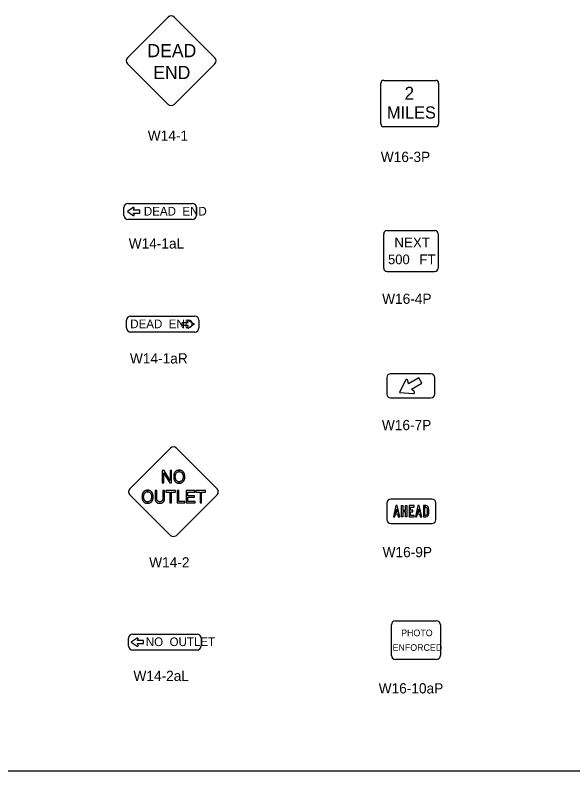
# Model space of a CAD drawing. Extents: x 42133 to 45533, y 41351 to 47951.
# Drawn here: x 44235 to 44644, y 45801 to 46356 of the extents above; entities that cross this region are included whole.
import ezdxf

# ---------------------------------------------------------------- set-up
doc = ezdxf.new("R2010")
doc.units = 0
doc.layers.add('P_ODOT_PLAN_Border', color=7, linetype='Continuous')
doc.layers.add('P_TRAF_SIGN_SignDetails', color=7, linetype='Continuous')

msp = doc.modelspace()

# ---------------------------------------------------------------- linework, layer by layer
at = {"layer": 'P_ODOT_PLAN_Border'}
msp.add_lwpolyline([(43908.34, 45801.35), (45508.34, 45801.35), (45508.34, 46801.35), (43908.34, 46801.35)], close=True, dxfattribs=at)
at = {"layer": 'P_TRAF_SIGN_SignDetails'}
for p, q in [((44347.15, 46354.48), (44317.28, 46324.61)), ((44381.29, 46324.61), (44351.41, 46354.48)), ((44317.28, 46320.35), (44347.15, 46290.47)), ((44351.41, 46290.47), (44381.29, 46320.35)), ((44505.11, 46308.09), (44543.26, 46308.09)), ((44502.98, 46276.17), (44502.98, 46305.97)), ((44545.38, 46305.97), (44545.38, 46276.17)), ((44543.26, 46274.04), (44505.11, 46274.04)), ((44317.61, 46217.76), (44364.73, 46217.76)), ((44314.61, 46209.04), (44314.61, 46214.77)), ((44367.71, 46214.77), (44367.71, 46209.04)), ((44364.73, 46206.04), (44317.61, 46206.04)), ((44505.12, 46170.38), (44505.12, 46195.37)), ((44507.62, 46197.86), (44542.6, 46197.86)), ((44545.1, 46195.37), (44545.1, 46170.38)), ((44507.62, 46167.88), (44542.6, 46167.88)), ((44319.52, 46135.13), (44366.65, 46135.13)), ((44316.53, 46126.41), (44316.53, 46132.13)), ((44369.63, 46132.13), (44369.63, 46126.41)), ((44366.65, 46123.41), (44319.52, 46123.41)), ((44507.31, 46090.01), (44507.31, 46077.92)), ((44539.76, 46092.76), (44510.06, 46092.76)), ((44542.51, 46077.92), (44542.51, 46090.01)), ((44510.06, 46075.17), (44539.76, 46075.17)), ((44348.81, 46038.16), (44318.94, 46008.29)), ((44382.95, 46008.29), (44353.07, 46038.16)), ((44318.94, 46004.03), (44348.81, 45974.15)), ((44353.07, 45974.15), (44382.95, 46004.03)), ((44507.5, 45997.93), (44507.5, 45985.61)), ((44540.57, 46000.74), (44510.3, 46000.74)), ((44543.37, 45985.61), (44543.37, 45997.93)), ((44510.3, 45982.8), (44540.57, 45982.8)), ((44510.74, 45886.07), (44510.74, 45908.5)), ((44513.73, 45911.5), (44543.67, 45911.5)), ((44546.66, 45908.5), (44546.66, 45886.07)), ((44321.09, 45901.78), (44368.21, 45901.78)), ((44318.09, 45893.05), (44318.09, 45898.78)), ((44371.19, 45898.78), (44371.19, 45893.05)), ((44368.21, 45890.06), (44321.09, 45890.06)), ((44543.67, 45883.08), (44513.73, 45883.08))]:
    msp.add_line(p, q, dxfattribs=at)
for points in [[(44321.5, 46214.77), (44317.23, 46211.84), (44321.5, 46208.92)], [(44321.5, 46214.77), (44317.23, 46211.84), (44321.5, 46208.92)], [(44321.5, 46214.77), (44317.23, 46211.84), (44321.5, 46208.92)], [(44326.23, 46210.73), (44326.23, 46212.96), (44321.76, 46212.96), (44322.16, 46214.28)], [(44326.23, 46210.73), (44326.23, 46212.96), (44321.76, 46212.96), (44322.16, 46214.28)], [(44326.23, 46210.73), (44326.23, 46212.96), (44321.76, 46212.96), (44322.16, 46214.28)], [(44322.16, 46209.4), (44321.76, 46210.73), (44326.23, 46210.73)], [(44322.16, 46209.4), (44321.76, 46210.73), (44326.23, 46210.73)], [(44322.16, 46209.4), (44321.76, 46210.73), (44326.23, 46210.73)], [(44357.3, 46128.1), (44357.3, 46130.32), (44361.78, 46130.32), (44361.37, 46131.65)], [(44357.3, 46128.1), (44357.3, 46130.32), (44361.78, 46130.32), (44361.37, 46131.65)], [(44357.3, 46128.1), (44357.3, 46130.32), (44361.78, 46130.32), (44361.37, 46131.65)], [(44362.03, 46132.14), (44366.3, 46129.21), (44362.03, 46126.29)], [(44362.03, 46132.14), (44366.3, 46129.21), (44362.03, 46126.29)], [(44362.03, 46132.14), (44366.3, 46129.21), (44362.03, 46126.29)], [(44361.37, 46126.77), (44361.78, 46128.1), (44357.3, 46128.1)], [(44361.37, 46126.77), (44361.78, 46128.1), (44357.3, 46128.1)], [(44361.37, 46126.77), (44361.78, 46128.1), (44357.3, 46128.1)], [(44521.12, 46088.14), (44516.75, 46079.01), (44526.84, 46078.24)], [(44533.07, 46085.92), (44530.9, 46089.69), (44523.32, 46085.32), (44522.71, 46087.96)], [(44527.48, 46079.7), (44525.49, 46081.55), (44533.07, 46085.92)], [(44536.11, 45988.89), (44535.23, 45988.89), (44535.23, 45995.99), (44534.2, 45995.99), (44534.2, 45987.74), (44535.23, 45987.74), (44536.11, 45987.74)], [(44536.11, 45995.99), (44535.23, 45995.99), (44535.23, 45994.84), (44536.11, 45994.84)], [(44324.3, 45898.78), (44320.03, 45895.86), (44324.3, 45892.93)], [(44324.3, 45898.78), (44320.03, 45895.86), (44324.3, 45892.93)], [(44324.3, 45898.78), (44320.03, 45895.86), (44324.3, 45892.93)], [(44329.03, 45894.74), (44329.03, 45896.97), (44324.55, 45896.97), (44324.96, 45898.3)], [(44329.03, 45894.74), (44329.03, 45896.97), (44324.55, 45896.97), (44324.96, 45898.3)], [(44329.03, 45894.74), (44329.03, 45896.97), (44324.55, 45896.97), (44324.96, 45898.3)], [(44324.96, 45893.42), (44324.55, 45894.74), (44329.03, 45894.74)], [(44324.96, 45893.42), (44324.55, 45894.74), (44329.03, 45894.74)], [(44324.96, 45893.42), (44324.55, 45894.74), (44329.03, 45894.74)]]:
    msp.add_lwpolyline(points, dxfattribs=at)
for points in [[(44342.76, 46021.78), (44342.76, 46012.69), (44343.88, 46012.69), (44343.88, 46020.06), (44343.94, 46019.89), (44344.02, 46019.71), (44344.11, 46019.54), (44344.2, 46019.38), (44348.32, 46012.69), (44349.6, 46012.69), (44349.6, 46021.78), (44348.48, 46021.78), (44348.48, 46014.41), (44348.39, 46014.61), (44348.3, 46014.81), (44348.2, 46015), (44348.08, 46015.18), (44344.05, 46021.78)], [(44355.18, 46022.02), (44354.97, 46022.02), (44354.75, 46022.01), (44354.53, 46021.99), (44354.32, 46021.96), (44354.03, 46021.9), (44353.75, 46021.81), (44353.48, 46021.7), (44353.22, 46021.57), (44352.96, 46021.42), (44352.73, 46021.25), (44352.5, 46021.06), (44352.29, 46020.85), (44352.07, 46020.59), (44351.87, 46020.32), (44351.7, 46020.03), (44351.55, 46019.73), (44351.42, 46019.41), (44351.31, 46019.09), (44351.23, 46018.76), (44351.17, 46018.42), (44351.14, 46018.13), (44351.11, 46017.83), (44351.1, 46017.53), (44352.31, 46017.51), (44352.32, 46017.78), (44352.35, 46018.05), (44352.4, 46018.32), (44352.45, 46018.59), (44352.52, 46018.85), (44352.61, 46019.12), (44352.71, 46019.37), (44352.77, 46019.51), (44352.85, 46019.65), (44352.93, 46019.78), (44353.02, 46019.91), (44353.12, 46020.03), (44353.22, 46020.14), (44353.33, 46020.25), (44353.44, 46020.35), (44353.56, 46020.45), (44353.69, 46020.53), (44353.82, 46020.61), (44353.95, 46020.69), (44354.09, 46020.75), (44354.23, 46020.8), (44354.37, 46020.85), (44354.52, 46020.89), (44354.69, 46020.91), (44354.85, 46020.94), (44355.02, 46020.95), (44355.18, 46020.95)], [(44355.18, 46020.95), (44355.42, 46020.95), (44355.65, 46020.92), (44355.88, 46020.87), (44356.1, 46020.81), (44356.32, 46020.72), (44356.53, 46020.61), (44356.74, 46020.49), (44356.92, 46020.34), (44357.04, 46020.24), (44357.15, 46020.14), (44357.25, 46020.02), (44357.35, 46019.9), (44357.43, 46019.78), (44357.52, 46019.64), (44357.59, 46019.51), (44357.66, 46019.37), (44357.75, 46019.12), (44357.84, 46018.85), (44357.91, 46018.59), (44357.96, 46018.32), (44358.01, 46018.05), (44358.04, 46017.78), (44358.05, 46017.51), (44358.05, 46017.23), (44358.05, 46016.96), (44359.26, 46016.93), (44359.27, 46017.23), (44359.26, 46017.53), (44359.25, 46017.83), (44359.22, 46018.13), (44359.18, 46018.42), (44359.15, 46018.65), (44359.1, 46018.87), (44359.05, 46019.1), (44358.98, 46019.32), (44358.9, 46019.53), (44358.81, 46019.75), (44358.71, 46019.95), (44358.61, 46020.15), (44358.43, 46020.42), (44358.24, 46020.68), (44358.03, 46020.91), (44357.79, 46021.13), (44357.55, 46021.33), (44357.28, 46021.5), (44357.01, 46021.65), (44356.72, 46021.77), (44356.53, 46021.83), (44356.35, 46021.89), (44356.15, 46021.93), (44355.96, 46021.97), (44355.77, 46022), (44355.57, 46022.02), (44355.38, 46022.02), (44355.18, 46022.02)], [(44355.18, 46013.5), (44354.95, 46013.51), (44354.72, 46013.53), (44354.49, 46013.58), (44354.27, 46013.65), (44354.05, 46013.73), (44353.84, 46013.84), (44353.64, 46013.97), (44353.45, 46014.11), (44353.34, 46014.21), (44353.23, 46014.32), (44353.12, 46014.43), (44353.03, 46014.56), (44352.93, 46014.68), (44352.85, 46014.82), (44352.78, 46014.95), (44352.71, 46015.1), (44352.61, 46015.35), (44352.52, 46015.61), (44352.46, 46015.87), (44352.4, 46016.14), (44352.36, 46016.41), (44352.33, 46016.68), (44352.31, 46016.96), (44352.31, 46017.23), (44352.31, 46017.51), (44351.1, 46017.53), (44351.1, 46017.23), (44351.1, 46016.93), (44351.11, 46016.64), (44351.14, 46016.34), (44351.17, 46016.04), (44351.21, 46015.82), (44351.25, 46015.6), (44351.31, 46015.38), (44351.38, 46015.17), (44351.45, 46014.96), (44351.53, 46014.76), (44351.62, 46014.56), (44351.72, 46014.36), (44351.84, 46014.17), (44351.96, 46013.99), (44352.09, 46013.82), (44352.24, 46013.66), (44352.39, 46013.5), (44352.55, 46013.35), (44352.72, 46013.22), (44352.89, 46013.09), (44353.07, 46012.97), (44353.26, 46012.87), (44353.45, 46012.77), (44353.64, 46012.69), (44353.83, 46012.63), (44354.02, 46012.58), (44354.21, 46012.54), (44354.4, 46012.5), (44354.6, 46012.47), (44354.79, 46012.45), (44354.99, 46012.44), (44355.18, 46012.44)], [(44355.18, 46012.44), (44355.4, 46012.45), (44355.61, 46012.46), (44355.82, 46012.48), (44356.04, 46012.51), (44356.32, 46012.56), (44356.6, 46012.65), (44356.88, 46012.75), (44357.14, 46012.88), (44357.39, 46013.03), (44357.64, 46013.2), (44357.87, 46013.39), (44358.08, 46013.6), (44358.29, 46013.86), (44358.49, 46014.14), (44358.66, 46014.43), (44358.81, 46014.73), (44358.94, 46015.05), (44359.05, 46015.37), (44359.13, 46015.7), (44359.18, 46016.04), (44359.22, 46016.34), (44359.25, 46016.64), (44359.26, 46016.93), (44358.05, 46016.96), (44358.04, 46016.68), (44358.01, 46016.41), (44357.96, 46016.14), (44357.91, 46015.87), (44357.84, 46015.61), (44357.75, 46015.35), (44357.66, 46015.1), (44357.59, 46014.95), (44357.51, 46014.82), (44357.43, 46014.68), (44357.34, 46014.56), (44357.24, 46014.43), (44357.14, 46014.32), (44357.03, 46014.21), (44356.92, 46014.11), (44356.79, 46014.01), (44356.67, 46013.93), (44356.54, 46013.85), (44356.4, 46013.78), (44356.26, 46013.71), (44356.12, 46013.66), (44355.98, 46013.61), (44355.83, 46013.58), (44355.67, 46013.54), (44355.51, 46013.52), (44355.35, 46013.51), (44355.18, 46013.5)], [(44331.96, 46007.29), (44331.74, 46007.29), (44331.52, 46007.28), (44331.31, 46007.26), (44331.09, 46007.23), (44330.81, 46007.17), (44330.53, 46007.08), (44330.26, 46006.97), (44329.99, 46006.84), (44329.74, 46006.69), (44329.5, 46006.52), (44329.27, 46006.33), (44329.06, 46006.12), (44328.85, 46005.86), (44328.65, 46005.59), (44328.47, 46005.3), (44328.32, 46005), (44328.19, 46004.68), (44328.08, 46004.36), (44328, 46004.03), (44327.95, 46003.69), (44327.91, 46003.39), (44327.89, 46003.1), (44327.88, 46002.8), (44329.09, 46002.78), (44329.1, 46003.05), (44329.13, 46003.32), (44329.17, 46003.59), (44329.23, 46003.86), (44329.3, 46004.12), (44329.38, 46004.38), (44329.48, 46004.64), (44329.55, 46004.78), (44329.62, 46004.92), (44329.71, 46005.05), (44329.8, 46005.18), (44329.89, 46005.3), (44330, 46005.41), (44330.1, 46005.52), (44330.22, 46005.62), (44330.34, 46005.72), (44330.46, 46005.8), (44330.59, 46005.88), (44330.73, 46005.96), (44330.87, 46006.02), (44331.01, 46006.07), (44331.15, 46006.12), (44331.3, 46006.16), (44331.46, 46006.18), (44331.63, 46006.2), (44331.79, 46006.22), (44331.96, 46006.22)], [(44331.96, 46006.22), (44332.19, 46006.22), (44332.42, 46006.19), (44332.65, 46006.14), (44332.88, 46006.08), (44333.1, 46005.99), (44333.31, 46005.88), (44333.51, 46005.76), (44333.7, 46005.61), (44333.82, 46005.51), (44333.92, 46005.41), (44334.03, 46005.29), (44334.12, 46005.17), (44334.21, 46005.05), (44334.29, 46004.91), (44334.37, 46004.78), (44334.43, 46004.64), (44334.53, 46004.38), (44334.61, 46004.12), (44334.69, 46003.86), (44334.74, 46003.59), (44334.78, 46003.32), (44334.81, 46003.05), (44334.83, 46002.78), (44334.83, 46002.5), (44334.83, 46002.23), (44336.04, 46002.2), (44336.04, 46002.5), (44336.04, 46002.8), (44336.02, 46003.1), (44335.99, 46003.39), (44335.96, 46003.69), (44335.92, 46003.92), (44335.88, 46004.14), (44335.82, 46004.37), (44335.75, 46004.59), (44335.67, 46004.8), (44335.59, 46005.02), (44335.49, 46005.22), (44335.38, 46005.42), (44335.21, 46005.69), (44335.01, 46005.95), (44334.8, 46006.18), (44334.57, 46006.4), (44334.32, 46006.6), (44334.06, 46006.77), (44333.78, 46006.92), (44333.49, 46007.04), (44333.31, 46007.1), (44333.12, 46007.16), (44332.93, 46007.2), (44332.74, 46007.24), (44332.54, 46007.27), (44332.35, 46007.29), (44332.15, 46007.29), (44331.96, 46007.29)], [(44337.53, 46007.05), (44337.53, 46001.41), (44337.53, 46001.04), (44337.55, 46000.67), (44337.59, 46000.35), (44337.65, 46000.03), (44337.74, 45999.72), (44337.85, 45999.42), (44337.97, 45999.18), (44338.11, 45998.95), (44338.28, 45998.74), (44338.46, 45998.54), (44338.65, 45998.37), (44338.87, 45998.21), (44339.09, 45998.08), (44339.33, 45997.97), (44339.51, 45997.91), (44339.7, 45997.86), (44339.88, 45997.81), (44340.07, 45997.77), (44340.26, 45997.74), (44340.45, 45997.72), (44340.64, 45997.71), (44340.83, 45997.71), (44341.03, 45997.71), (44341.24, 45997.73), (44341.44, 45997.74), (44341.64, 45997.77), (44341.83, 45997.81), (44342.03, 45997.86), (44342.23, 45997.91), (44342.42, 45997.97), (44342.59, 45998.04), (44342.75, 45998.12), (44342.91, 45998.2), (44343.07, 45998.3), (44343.21, 45998.41), (44343.36, 45998.53), (44343.49, 45998.65), (44343.62, 45998.79), (44343.74, 45998.93), (44343.84, 45999.08), (44343.95, 45999.24), (44344.04, 45999.4), (44344.12, 45999.57), (44344.18, 45999.75), (44344.25, 45999.93), (44344.29, 46000.11), (44344.35, 46000.43), (44344.38, 46000.76), (44344.4, 46001.08), (44344.4, 46001.41), (44344.4, 46007.05), (44343.22, 46007.05), (44343.22, 46001.4), (44343.22, 46001.14), (44343.2, 46000.88), (44343.18, 46000.67), (44343.14, 46000.45), (44343.08, 46000.24), (44343.01, 46000.04), (44342.93, 45999.88), (44342.84, 45999.73), (44342.72, 45999.59), (44342.61, 45999.46), (44342.47, 45999.34), (44342.33, 45999.24), (44342.18, 45999.16), (44342.02, 45999.09), (44341.77, 45999), (44341.5, 45998.94), (44341.23, 45998.91), (44340.96, 45998.9), (44340.7, 45998.9), (44340.44, 45998.93), (44340.19, 45998.99), (44339.93, 45999.07), (44339.82, 45999.12), (44339.71, 45999.17), (44339.61, 45999.23), (44339.51, 45999.3), (44339.41, 45999.37), (44339.32, 45999.46), (44339.23, 45999.54), (44339.15, 45999.64), (44339.08, 45999.73), (44339.01, 45999.84), (44338.95, 45999.95), (44338.9, 46000.06), (44338.86, 46000.18), (44338.82, 46000.3), (44338.79, 46000.42), (44338.77, 46000.54), (44338.74, 46000.75), (44338.72, 46000.97), (44338.71, 46001.19), (44338.71, 46001.4), (44338.71, 46007.05)], [(44345.42, 46007.05), (44345.42, 46005.95), (44348.38, 46005.95), (44348.38, 45997.96), (44349.57, 45997.96), (44349.57, 46005.95), (44352.52, 46005.95), (44352.52, 46007.05)], [(44353.61, 46007.05), (44353.61, 45997.96), (44359.3, 45997.96), (44359.3, 45999.11), (44354.8, 45999.11), (44354.8, 46007.05)], [(44360.29, 46007.05), (44360.29, 45997.96), (44366.81, 45997.96), (44366.81, 45999.1), (44361.46, 45999.1), (44361.46, 46002.15), (44366.3, 46002.15), (44366.3, 46003.21), (44361.46, 46003.21), (44361.46, 46005.93), (44366.71, 46005.93), (44366.71, 46007.05)], [(44367.45, 46007.05), (44367.45, 46005.95), (44370.41, 46005.95), (44370.41, 45997.96), (44371.6, 45997.96), (44371.6, 46005.95), (44374.55, 46005.95), (44374.55, 46007.05)], [(44331.96, 45998.77), (44331.72, 45998.78), (44331.49, 45998.8), (44331.27, 45998.85), (44331.04, 45998.92), (44330.83, 45999), (44330.61, 45999.11), (44330.42, 45999.24), (44330.23, 45999.38), (44330.11, 45999.48), (44330, 45999.59), (44329.9, 45999.7), (44329.8, 45999.83), (44329.71, 45999.95), (44329.63, 46000.09), (44329.55, 46000.22), (44329.48, 46000.37), (44329.39, 46000.62), (44329.3, 46000.88), (44329.23, 46001.14), (44329.17, 46001.41), (44329.13, 46001.68), (44329.1, 46001.95), (44329.09, 46002.23), (44329.09, 46002.5), (44329.09, 46002.78), (44327.88, 46002.8), (44327.87, 46002.5), (44327.88, 46002.2), (44327.89, 46001.91), (44327.91, 46001.61), (44327.95, 46001.31), (44327.98, 46001.09), (44328.03, 46000.87), (44328.08, 46000.65), (44328.15, 46000.44), (44328.22, 46000.23), (44328.3, 46000.03), (44328.39, 45999.83), (44328.5, 45999.63), (44328.61, 45999.44), (44328.74, 45999.26), (44328.87, 45999.09), (44329.01, 45998.93), (44329.16, 45998.77), (44329.32, 45998.62), (44329.49, 45998.49), (44329.66, 45998.36), (44329.84, 45998.24), (44330.03, 45998.14), (44330.22, 45998.04), (44330.42, 45997.96), (44330.61, 45997.9), (44330.8, 45997.85), (44330.99, 45997.81), (44331.18, 45997.77), (44331.37, 45997.74), (44331.57, 45997.72), (44331.76, 45997.71), (44331.96, 45997.71)], [(44331.96, 45997.71), (44332.17, 45997.71), (44332.39, 45997.73), (44332.6, 45997.75), (44332.81, 45997.77), (44333.1, 45997.83), (44333.38, 45997.92), (44333.65, 45998.02), (44333.92, 45998.15), (44334.17, 45998.3), (44334.41, 45998.47), (44334.64, 45998.66), (44334.85, 45998.87), (44335.07, 45999.13), (44335.26, 45999.4), (44335.44, 45999.7), (44335.59, 46000), (44335.72, 46000.31), (44335.82, 46000.64), (44335.9, 46000.97), (44335.96, 46001.31), (44335.99, 46001.61), (44336.02, 46001.91), (44336.04, 46002.2), (44334.83, 46002.23), (44334.81, 46001.95), (44334.78, 46001.68), (44334.74, 46001.41), (44334.69, 46001.14), (44334.61, 46000.88), (44334.53, 46000.62), (44334.43, 46000.37), (44334.36, 46000.22), (44334.29, 46000.09), (44334.21, 45999.95), (44334.12, 45999.83), (44334.02, 45999.7), (44333.92, 45999.59), (44333.81, 45999.48), (44333.69, 45999.38), (44333.57, 45999.28), (44333.44, 45999.2), (44333.31, 45999.12), (44333.18, 45999.05), (44333.04, 45998.98), (44332.9, 45998.93), (44332.75, 45998.88), (44332.61, 45998.85), (44332.45, 45998.81), (44332.28, 45998.79), (44332.12, 45998.78), (44331.96, 45998.77)], [(44513.99, 45991.1), (44513.75, 45989.95), (44515.33, 45989.95), (44515.81, 45987.74), (44516.86, 45987.74), (44515.09, 45995.99), (44513.99, 45995.99), (44512.22, 45987.74), (44513.27, 45987.74), (44514.54, 45993.64), (44515.09, 45991.1)], [(44518.11, 45995.99), (44519.13, 45995.99), (44519.13, 45992.68), (44521.14, 45992.68), (44521.14, 45995.99), (44522.17, 45995.99), (44522.17, 45987.74), (44521.14, 45987.74), (44521.14, 45991.53), (44519.13, 45991.53), (44519.13, 45987.74), (44518.11, 45987.74)], [(44524.76, 45988.89), (44524.76, 45991.53), (44526.37, 45991.53), (44526.37, 45992.68), (44524.76, 45992.68), (44524.76, 45994.84), (44527.47, 45994.84), (44527.47, 45995.99), (44523.74, 45995.99), (44523.74, 45987.74), (44527.47, 45987.74), (44527.47, 45988.89)], [(44530.09, 45991.1), (44529.85, 45989.95), (44531.43, 45989.95), (44531.91, 45987.74), (44532.96, 45987.74), (44531.18, 45995.99), (44530.09, 45995.99), (44528.31, 45987.74), (44529.37, 45987.74), (44530.64, 45993.64), (44531.18, 45991.1)]]:
    msp.add_lwpolyline(points, close=True, dxfattribs=at)
for centre, radius, start, end in [((44349.28, 46352.35), 3.01, 45, 135), ((44319.4, 46322.47), 3.01, 135, 225), ((44379.16, 46322.47), 3.01, 315, 45), ((44505.11, 46305.97), 2.12, 90, 180), ((44543.26, 46305.97), 2.12, 0, 90), ((44349.28, 46292.6), 3.01, 225, 315), ((44505.11, 46276.17), 2.12, 180, 270), ((44543.26, 46276.17), 2.12, 270, 360), ((44317.61, 46214.77), 2.99, 90, 180), ((44364.73, 46214.77), 2.99, 360, 90), ((44321.75, 46214.41), 0.433, 342.9427, 124.3997), ((44321.75, 46214.41), 0.433, 342.9427, 124.3997), ((44321.75, 46214.41), 0.433, 342.9427, 124.3997), ((44317.61, 46209.04), 2.99, 180, 270), ((44321.75, 46209.28), 0.433, 235.6003, 17.0573), ((44321.75, 46209.28), 0.433, 235.6003, 17.0573), ((44321.75, 46209.28), 0.433, 235.6003, 17.0573), ((44364.73, 46209.04), 2.99, 270, 360), ((44507.62, 46195.37), 2.5, 90, 180), ((44542.6, 46195.37), 2.5, 360, 90), ((44507.62, 46170.38), 2.5, 180, 270), ((44542.6, 46170.38), 2.5, 270, 0), ((44319.52, 46132.13), 2.99, 90, 180), ((44366.65, 46132.13), 2.99, 360, 90), ((44361.78, 46131.78), 0.433, 55.6003, 197.0573), ((44361.78, 46131.78), 0.433, 55.6003, 197.0573), ((44361.78, 46131.78), 0.433, 55.6003, 197.0573), ((44319.52, 46126.4), 2.99, 180, 270), ((44361.78, 46126.64), 0.433, 162.9427, 304.3997), ((44361.78, 46126.64), 0.433, 162.9427, 304.3997), ((44361.78, 46126.64), 0.433, 162.9427, 304.3997), ((44366.65, 46126.4), 2.99, 270, 360), ((44510.06, 46090.01), 2.75, 90, 180), ((44539.76, 46090.01), 2.75, 0, 90), ((44521.88, 46087.77), 0.846, 12.9427, 154.3997), ((44526.9, 46079.08), 0.846, 265.6003, 47.0573), ((44510.06, 46077.92), 2.75, 180, 270), ((44539.76, 46077.92), 2.75, 270, 0), ((44350.94, 46036.03), 3.01, 45, 135), ((44321.06, 46006.15), 3.01, 135, 225), ((44380.82, 46006.15), 3.01, 315, 45), ((44510.3, 45997.93), 2.8, 90, 180), ((44540.57, 45997.93), 2.8, 0, 90), ((44510.3, 45985.61), 2.8, 180, 270), ((44540.57, 45985.61), 2.8, 270, 0), ((44350.94, 45976.28), 3.01, 225, 315), ((44513.73, 45908.5), 2.99, 90, 180), ((44543.67, 45908.5), 2.99, 360, 90), ((44321.09, 45898.78), 2.99, 90, 180), ((44368.21, 45898.78), 2.99, 360, 90), ((44324.54, 45898.42), 0.433, 342.9427, 124.3997), ((44324.54, 45898.42), 0.433, 342.9427, 124.3997), ((44324.54, 45898.42), 0.433, 342.9427, 124.3997), ((44321.09, 45893.05), 2.99, 180, 270), ((44324.54, 45893.29), 0.433, 235.6003, 17.0573), ((44324.54, 45893.29), 0.433, 235.6003, 17.0573), ((44324.54, 45893.29), 0.433, 235.6003, 17.0573), ((44368.21, 45893.05), 2.99, 270, 360), ((44513.74, 45886.07), 2.99, 180, 270), ((44543.68, 45886.07), 2.99, 270, 360)]:
    msp.add_arc(centre, radius, start, end, dxfattribs=at)
for centre, major_axis, start_param, end_param in [((44536.16, 45994.02), (0, 1.97), 5.256629, 6.310275), ((44536.11, 45993.94), (0, 0.893), 5.295674, 6.281994), ((44535.55, 45993.29), (0, 1.79), 4.84938, 5.407144), ((44535.55, 45990.44), (0, -1.79), 0.876041, 1.433806), ((44526.03, 45991.65), (0, 12.66), 4.728786, 4.861202), ((44526.03, 45992.07), (0, -12.66), 1.421983, 1.554399), ((44535.3, 45993.17), (0, 3.24), 4.80999, 5.326889), ((44535.3, 45990.55), (0, -3.24), 0.956296, 1.473195), ((44529, 45991.85), (0, 10.46), 4.713872, 4.870248), ((44529, 45991.88), (0, -10.46), 1.412937, 1.569314), ((44536.11, 45989.78), (0, -0.893), 0.001192, 0.987511), ((44536.16, 45989.7), (0, -1.97), 6.256095, 7.309742)]:
    msp.add_ellipse(centre, major_axis=major_axis, ratio=0.88627, start_param=start_param, end_param=end_param, dxfattribs=at)

# ---------------------------------------------------------------- texts
for s, height, p in [('DEAD', 9.656, (44331.82, 46325.09)), ('END', 9.656, (44336.09, 46309.07)), ('2', 9.4, (44520.39, 46293.97)), ('MILES', 8.952, (44507.46, 46280.05)), ('W14-1', 7.5, (44332.13, 46263.8)), ('W16-3P', 7.5, (44502.98, 46248.2)), ('DEAD  END', 6.335, (44329.25, 46208.92)), ('W14-1aL', 7.5, (44318.12, 46184.66)), ('NEXT', 7.323, (44512.91, 46185.45)), ('500', 7.125, (44508.28, 46173.18)), ('FT', 7.323, (44531.19, 46173.06)), ('W16-4P', 7.5, (44503.96, 46144.07)), ('DEAD  END', 6.335, (44319.24, 46126.24)), ('W14-1aR', 7.5, (44319.03, 46100.32)), ('W16-7P', 7.5, (44503.76, 46051.39)), ('W16-9P', 7.5, (44504.29, 45958.16)), ('W14-2', 7.5, (44333.14, 45950.64)), ('PHOTO', 4.853, (44517.9, 45900.2)), ('NO  OUTLET', 6.335, (44330.67, 45892.93)), ('ENFORCED', 4.853, (44511.61, 45889.46)), ('W14-2aL', 7.5, (44321.61, 45867.33)), ('W16-10aP', 7.5, (44501.41, 45858.2))]:
    msp.add_text(s, height=height, dxfattribs=at).set_placement(p)

doc.saveas('drawing.dxf')
